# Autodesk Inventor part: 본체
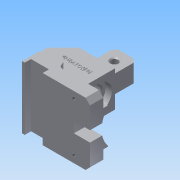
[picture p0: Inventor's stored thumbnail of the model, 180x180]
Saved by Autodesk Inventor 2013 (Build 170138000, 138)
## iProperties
Created: 2016-11
Part Number: 본체
Material: 알루미늄 6061
Document SubType Name: Modeling
Designer: user
Density: 2.71 g/cm^3
Mass: 462.813 g
Surface Area: 317.449 cm^2
Volume: 170.78 cm^3
Author: user
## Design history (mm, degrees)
sketch "스케치1"
  geometry: L1 (13, 0)-(63, 0); L2 (63, 0)-(63, -15); L3 (-13, -15)-(-13, 0); L4 (-10, -15)-(-10, -8); L5 (-10, -8)-(10, -8); L6 (10, -8)-(10, -15); L7 (63, -15)-(10, -15); L8 (-10, -15)-(-13, -15); A1 r 13 centre (0, 0) between (13, 0) and (-13, 0); 1 further point
  constraints: 16 end point, 5 parallel, 2 perpendicular, 2 point on circle, 1 centre point, 1 coincident, 1 collinear, 1 horizontal, 1 tangent
  dimensions: "d0" = 26 diameter of A1; "d1" = 7 distance between parallel lines of L5 L8; "d2" = 15 distance between parallel lines of L7 L1; "d3" = 3 distance between parallel lines of L4 L3; "d4" = 20 distance between parallel lines of L6 L4; "d5" = 63 distance from line of L2 point (0, 0); "d6" = 15 distance from line of point (0, 0) L7
extrude "돌출1" new body sketch "스케치1" stored distance "d7" = 70; taper "d8" = 0 deg
sketch "스케치2"
  geometry: L1 (-13, -15)-(-13, 0) reference; L2 (-13, -3)-(-27, -3); L3 (-27, -3)-(-27, 27); L4 (-27, 27)-(-9, 45); L5 (-9, 45)-(1, 45); L6 (1, 45)-(1, 75); L7 (1, 75)-(26, 75); L8 (26, 75)-(26, 45); L9 (26, 45)-(31, 45); L10 (31, 45)-(31, 5); L11 (31, 5)-(63, 5); L12 (63, 5)-(63, 0); L13 (63, -15)-(10, -15) reference; L14 (63, 0)-(63, -15) reference; L15 (-10, -15)-(-13, -15) reference; L16 (-13, -3)-(63, -3); 1 further point
  constraints: 24 end point, 6 parallel, 5 perpendicular, 2 collinear, 2 point on line
  dimensions: "d9" = 20 distance between parallel lines of L13 L11; "d10" = 58 distance between parallel lines of L10 L3; "d11" = 90 distance between parallel lines of L14 L3; "d12" = 5 distance between parallel lines of L10 L8; "d13" = 25 distance between parallel lines of L6 L8; "d14" = 18 horizontal distance of L3.end L4.end; "d15" = 45 deg angle of L5 L4; "d16" = 60 distance between parallel lines of L15 L5; "d17" = 90 distance between parallel lines of L15 L7; "d18" = 12 distance between parallel lines of L15 L2
extrude "돌출2" join sketch "스케치2" stored distance "d19" = 40; taper "d20" = 0 deg
sketch "스케치3"
  geometry: L1 (-27, 27)-(31, 27); L2 (-13, -3)-(-27, -3) reference; L3 (-27, -3)-(-27, 27) reference; L4 (-27, 27)-(-27, 37); L5 (-27, 37)-(24, 37); L6 (24, 37)-(24, 41.5); L7 (24, 41.5)-(31, 41.5); L8 (31, 45)-(31, 5) reference; L9 (31, 41.5)-(31, 27); 1 further point
  constraints: 12 end point, 3 point on line, 2 parallel, 1 collinear, 1 horizontal, 1 perpendicular
  dimensions: "d21" = 30 distance between parallel lines of L2 L1; "d22" = 20 diameter of L5 L1; "d23" = 29 diameter of L7 L1; "d24" = 7 distance between parallel lines of L8 L6
revolve "회전1" sketch "스케치3" stored, may be unused: angle "d25" = 90 deg
sketch "스케치4"
  geometry: L1 (0, 30)-(40, 30) reference; L2 (0, 0)-(0, 30) reference; L3 (0, 0)-(40, 0) reference; L4 (40, 30)-(40, 0) reference; L5 (0, 30)-(10, 30); L6 (10, 30)-(10, 0); L7 (10, 0)-(0, 0); L8 (0, 0)-(0, 30); L9 (0, 0)-(40, 0) reference; L10 (40, 30)-(30, 30); L11 (30, 30)-(30, 0); L12 (30, 0)-(40, 0); L13 (40, 0)-(40, 30); 1 further point
  constraints: 16 end point, 4 collinear, 4 parallel, 2 horizontal, 2 perpendicular, 2 point on line
  dimensions: "d26" = 10 distance between parallel lines of L2 L6; "d27" = 10 distance between parallel lines of L4 L11
extrude "돌출3" cut sketch "스케치4" distance "d28" = 40; taper "d29" = 0 deg
sketch "스케치5"
  geometry: L1 (-25, 0)-(-25, 30) reference; L2 (37, -60)-(-16, -60) reference; 2 further points
  dimensions: "d30" = 12.5 distance from line of L1 point (-12.5, 17); "d31" = 77 distance from line of L2 point (-12.5, 17)
hole "구멍1" sketch "스케치5" at (-12.5, 17) diameter "d32" = 8; stored, may be unused: countersink angle "d36" = 90 deg, drill point angle "d38" = 118 deg; dims "d33" = 6, "d34" = 4, "d35" = 2, "d37" = 8
sketch "스케치6"
  geometry: L1 (55, 15)-(70, 15) reference; L2 (15, 20)-(55, 20) reference; L3 (29, 13.627)-(29, 0); L4 (41, 13.627)-(41, 0); L5 (41, 0)-(29, 0); L6 (16.106, 20)-(53.894, 20); L7 (35, 0)-(35, 20); L8 (15, 20)-(55, 20) reference; C1 r 10 at (35, 42) reference; A1 r 29 centre (35, 42) between (16.106, 20) and (29, 13.627); A2 r 29 centre (35, 42) between (41, 13.627) and (53.894, 20); 1 further point
  constraints: 10 end point, 4 point on circle, 2 centre point, 2 midpoint, 2 point on line, 1 coincident, 1 collinear, 1 parallel, 1 vertical alignment, 1 other
  dimensions: "d40" = 12 distance between parallel lines of L4 L3; "d41" = 29 radius of A1; "d42" = 29 radius of A2; "d43" = 90 deg angle of L1 L4
extrude "돌출4" cut sketch "스케치6" distance "d44" = 18; taper "d45" = 0 deg
sketch "스케치7"
  geometry: L1 (50, -15)-(50, 0) reference; 2 further points
  dimensions: "d46" = 27.5 vertical distance of point (-13, -35) point (32, -7.5); "d47" = 18 distance from line of L1 point (32, -7.5)
hole "구멍2" sketch "스케치7" at (32, -7.5) diameter "d48" = 3.459; stored, may be unused: countersink angle "d52" = 90 deg, drill point angle "d54" = 118 deg; dims "d49" = 6, "d50" = 4, "d51" = 2, "d53" = 8
sketch "스케치8"
  geometry: L1 (31, 45)-(-9, 45) reference; L2 (31, 5)-(31, 45) reference; 1 further point
  constraints: 1 other
  dimensions: "d55" = 18 distance from line of L1 point (6, 27); "d56" = 25 distance from line of L2 point (6, 27)
feature "엠보싱1" sketch "스케치8" dims "d57" = 0.5, "d58" = 0
chamfer "모따기1" distance "d59" = 4; stored, may be unused: second distance "d60" = 2, angle "d61" = 45 deg
fillet "모깎기1" dims "d62" = 5
chamfer "모따기2" distance "d63" = 5; stored, may be unused: second distance "d64" = 2, angle "d65" = 45 deg
fillet "모깎기2" dims "d66" = 3
chamfer "모따기3" distance "d67" = 1; stored, may be unused: second distance "d68" = 2, angle "d69" = 45 deg
node "솔리드1"
mirror "대칭1"
other parameters: "d39" = 58
